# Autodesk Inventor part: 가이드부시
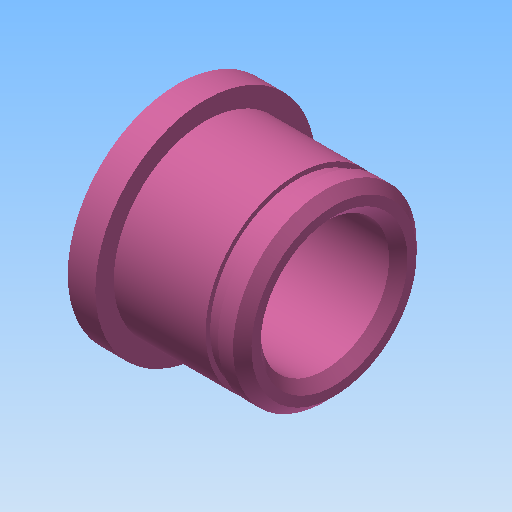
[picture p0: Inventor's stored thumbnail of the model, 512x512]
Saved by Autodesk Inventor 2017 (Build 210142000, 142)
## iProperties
Created: 2020-07
Part Number: 가이드부시
Material: 강철, 연강
Document SubType Name: Modeling
Designer: mduedu
Density: 7.86 g/cm^3
Appearance: 분홍색
Mass: 23.9234 g
Surface Area: 24.4489 cm^2
Volume: 3.04369 cm^3
Author: mduedu
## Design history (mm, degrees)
sketch "스케치1"
  geometry: L1 (0, 0)-(3, 0); L2 (3, 0)-(3, 12); L3 (3, 12)-(0, 12); L4 (0, 12)-(0, 0); L5 (3, 0)-(17, 0); L6 (17, 0)-(17, 10); L7 (17, 10)-(3, 10); L8 (3, 10)-(3, 0)
  constraints: 16 end point, 4 parallel, 2 horizontal, 2 perpendicular
  dimensions: "d0" = 24 diameter of L3 L1; "d2" = 20 diameter of L7 L5; "d3" = 3 distance of L2.end L3.end; "d4" = 17 distance between parallel lines of L6 L4
revolve "회전1" sketch "스케치1" stored, may be unused: angle "d5" = 90 deg
sketch "스케치2"
  geometry: C1 r 7 at (0, 0); 1 further point
  constraints: 1 centre point, 1 coincident
  dimensions: "d6" = 14 diameter of C1
extrude "돌출1" cut sketch "스케치2" stored distance "d7" = 10; taper "d8" = 0 deg
chamfer "모따기1" distance "d9" = 1; stored, may be unused: second distance "d10" = 2, angle "d11" = 45 deg
node "작업 평면1"
sketch "스케치3"
  geometry: C1 r 10 at (0, 0) reference; C2 r 9.5 at (0, 0); 1 further point
  constraints: 1 centre point, 1 coincident
  dimensions: "d13" = 19 diameter of C2
extrude "돌출2" cut sketch "스케치3" distance "d14" = 1.35; taper "d15" = 0 deg
node "솔리드1"
